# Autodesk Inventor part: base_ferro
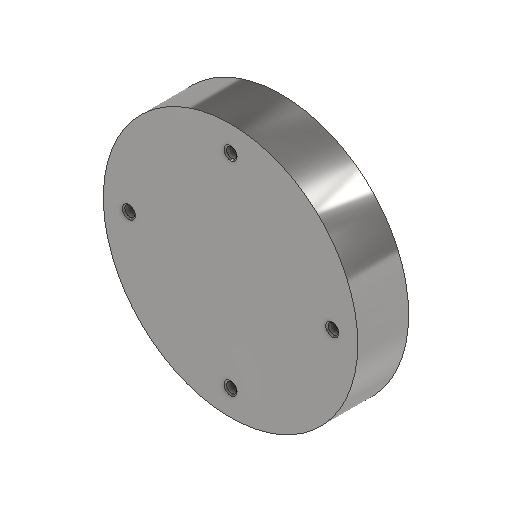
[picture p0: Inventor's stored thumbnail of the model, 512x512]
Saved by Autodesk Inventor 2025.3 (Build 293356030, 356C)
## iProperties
Created: 2025-09
Part Number: base_ferro
Material: Acciaio
Document SubType Name: Modeling
Designer: Ryzen5700u
Density: 7.85 g/cm^3
Appearance: Acciaio - Lucido
Mass: 1224.59 g
Surface Area: 229.088 cm^2
Volume: 155.999 cm^3
Author: Ryzen5700u
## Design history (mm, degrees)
sketch "Schizzo1"
  geometry: C1 r 50 at (0, 0); 1 further point
  constraints: 1 centre point, 1 coincident
  dimensions: "d0" = 100 diameter of C1
extrude "Estrusione1" new body sketch "Schizzo1" distance "d1" = 20; taper "d2" = 0 deg
sketch "Schizzo2"
  geometry: C1 r 2.75 at (0, 40) reference; 1 further point
hole "Foro1" sketch "Schizzo2" at (0, 40) diameter "d3" = 4.134; stored, may be unused: countersink angle "d7" = 90 deg, drill point angle "d9" = 118 deg; dims "d4" = 10, "d5" = 9, "d6" = 4, "d8" = 8
pattern_circular "Serie circolare1" dims angle "d11" = 360 deg
chamfer "Smusso1" distance "d13" = 0.5; stored, may be unused: second distance "d14" = 2, angle "d15" = 45 deg
node "Solido1"
node "Riferimento1"
